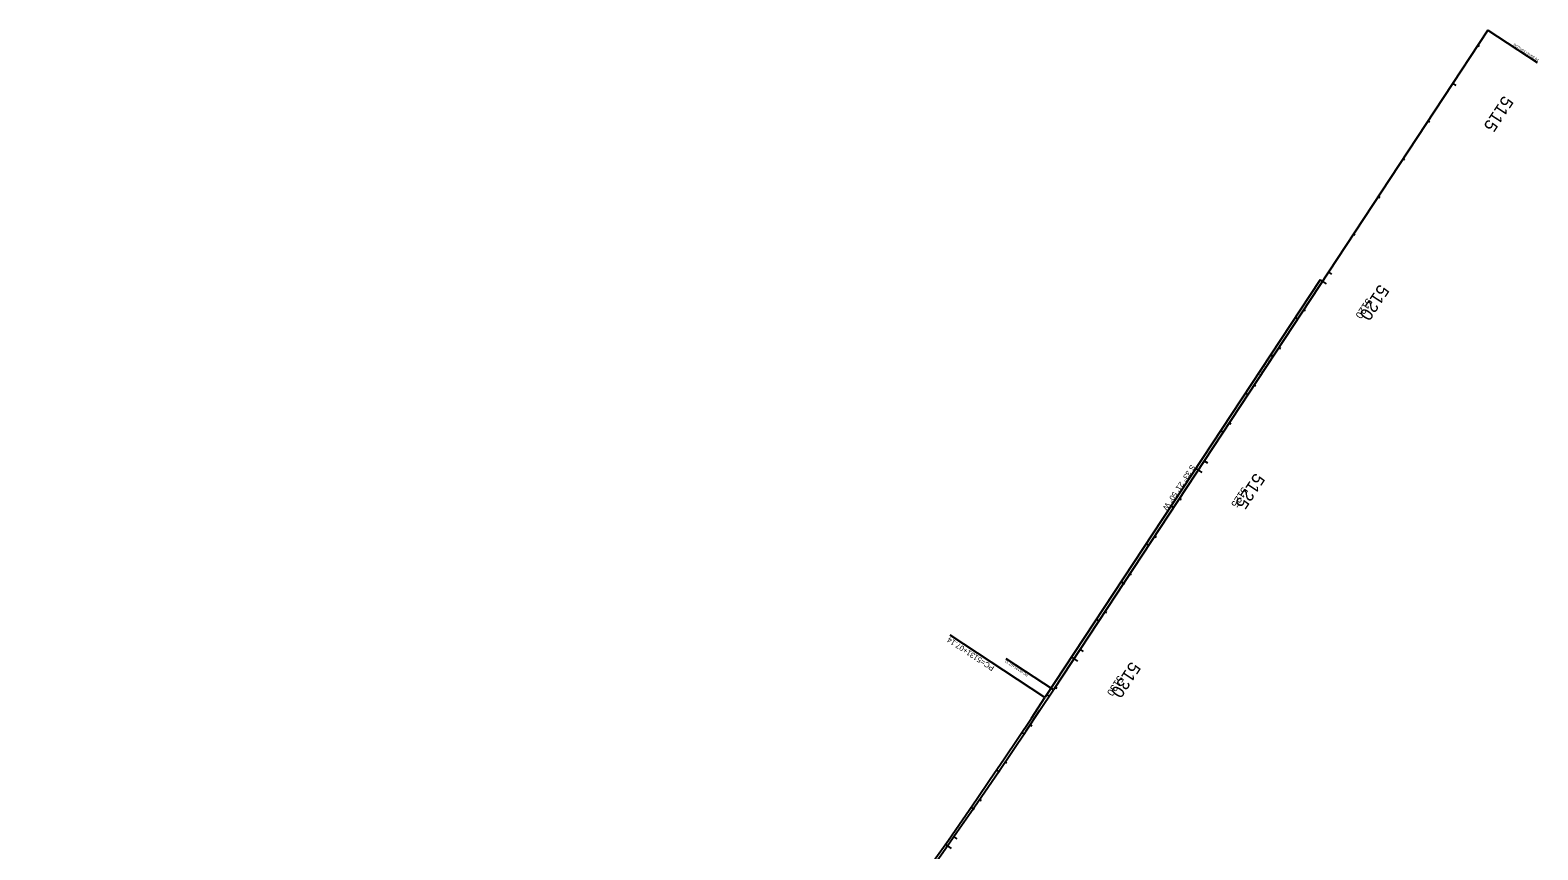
# Model space of a CAD drawing. Extents: x 2160876 to 2175990, y 601436 to 618246.
# Drawn here: x 2172654 to 2175990, y 616431 to 618246 of the extents above; entities that cross this region are included whole.
import ezdxf

# ---------------------------------------------------------------- set-up
doc = ezdxf.new("R2010")
doc.units = 0
for name, color, linetype in [('BNDY-ADJ', 7, 'Continuous'), ('RD_DTM_Major2', 7, 'Continuous'), ('RD_EX_BldgApp_Steps', 7, 'Continuous'), ('RD_EX_DV_TX_Prop', 7, 'Continuous'), ('RD_EX_Parking_Conc', 7, 'Continuous')]:
    doc.layers.add(name, color=color, linetype=linetype)

msp = doc.modelspace()

# ---------------------------------------------------------------- linework, layer by layer
at = {"layer": 'BNDY-ADJ'}
msp.add_line((2175508.7, 617693), (2174899.8, 616768.4), dxfattribs=at)
msp.add_arc((2162936.5, 624645.9), 14323.9, 312.71947, 326.63611, dxfattribs=at)
at = {"layer": 'RD_DTM_Major2'}
for p, q in [((2175508.7, 617693), (2175522.1, 617684.2)), ((2175453.7, 617609.5), (2175460.4, 617605.1)), ((2175398.7, 617526), (2175405.4, 617521.6)), ((2175343.7, 617442.5), (2175350.4, 617438.1)), ((2175288.7, 617359), (2175295.4, 617354.6)), ((2175233.7, 617275.4), (2175247.1, 617266.6)), ((2175178.7, 617191.9), (2175185.4, 617187.5)), ((2175123.7, 617108.4), (2175130.4, 617104)), ((2175068.7, 617024.9), (2175075.4, 617020.5)), ((2175013.7, 616941.4), (2175020.4, 616937)), ((2174958.7, 616857.8), (2174972.1, 616849)), ((2174903.7, 616774.3), (2174910.4, 616769.9)), ((2174848.5, 616691), (2174855.1, 616686.5)), ((2174792.7, 616608), (2174799.3, 616603.5)), ((2174736.3, 616525.4), (2174742.9, 616520.9)), ((2174679.3, 616443.2), (2174692.4, 616434.1))]:
    msp.add_line(p, q, dxfattribs=at)
at = {"layer": 'RD_EX_BldgApp_Steps'}
for p, q in [((2175880, 618245.7), (2174918.5, 616785.6)), ((2175880, 618245.7), (2175988.8, 618174.1)), ((2175857.4, 618211.4), (2175860.7, 618209.2)), ((2175802.4, 618127.9), (2175809.1, 618123.5)), ((2175747.4, 618044.4), (2175750.7, 618042.2)), ((2175692.4, 617960.9), (2175695.7, 617958.7)), ((2175637.4, 617877.3), (2175640.7, 617875.1)), ((2175582.4, 617793.8), (2175585.7, 617791.6)), ((2175527.4, 617710.3), (2175534.1, 617705.9)), ((2175472.4, 617626.8), (2175475.7, 617624.6)), ((2175417.4, 617543.3), (2175420.7, 617541.1)), ((2175362.4, 617459.7), (2175365.7, 617457.5)), ((2175307.4, 617376.2), (2175310.8, 617374)), ((2175252.4, 617292.7), (2175259.1, 617288.3)), ((2175197.4, 617209.2), (2175200.8, 617207)), ((2175142.4, 617125.7), (2175145.8, 617123.5)), ((2175087.4, 617042.1), (2175090.8, 617039.9)), ((2175032.4, 616958.6), (2175035.8, 616956.4)), ((2174918.5, 616785.6), (2174814.2, 616854.3)), ((2174977.4, 616875.1), (2174984.1, 616870.7)), ((2174922.4, 616791.6), (2174925.8, 616789.4)), ((2174867.2, 616708.2), (2174870.5, 616706)), ((2174811.4, 616625.3), (2174814.7, 616623)), ((2174755, 616542.7), (2174758.3, 616540.4)), ((2174698, 616460.5), (2174704.5, 616455.9))]:
    msp.add_line(p, q, dxfattribs=at)
msp.add_arc((2162955.1, 624663.2), 14324.1, 312.71947, 326.63611, dxfattribs=at)
at = {"layer": 'RD_EX_Parking_Conc'}
msp.add_line((2174899.8, 616768.4), (2174690.3, 616906.3), dxfattribs=at)

# ---------------------------------------------------------------- texts
at = {"layer": 'RD_EX_BldgApp_Steps'}
for s, height, rotation, p in [('POT=5113+58.91', 6, 326.6361, (2175935.4, 618211.7)), ('5115', 28, 236.6361, (2175915, 618102.5)), ('5120', 28, 236.6361, (2175640.1, 617685)), ('S 33° 21\' 50" W', 6, 56.6361, (2175373.9, 617479)), ('5125', 28, 236.6361, (2175365, 617267.3)), ('PC=5131+07.11', 6, 146.6361, (2174863.1, 616819.7)), ('5130', 28, 236.6361, (2175090.1, 616849.8))]:
    msp.add_text(s, height=height, rotation=rotation, dxfattribs=at).set_placement(p)
at = {"layer": 'RD_EX_DV_TX_Prop'}
for s, p in [('5120', (2175612.2, 617653.8)), ('5125', (2175336.9, 617235.8)), ('5130', (2175062.2, 616818.6))]:
    msp.add_text(s, height=16, rotation=236.6361, dxfattribs=at).set_placement(p)
at = {"layer": 'RD_EX_Parking_Conc'}
for s, rotation, p in [('S 33° 21\' 50" W', 236.6361, (2175223.4, 617285.2)), ('PC=5131+07.14', 146.6361, (2174789, 616836.5))]:
    msp.add_text(s, height=12, rotation=rotation, dxfattribs=at).set_placement(p)

doc.saveas('drawing.dxf')
